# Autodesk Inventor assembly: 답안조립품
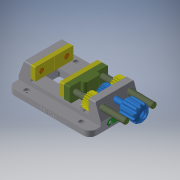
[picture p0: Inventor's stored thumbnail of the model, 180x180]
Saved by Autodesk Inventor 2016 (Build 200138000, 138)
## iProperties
Created: 2021-03
Part Number: 답안조립품
Material: 일반
Document SubType Name: Assembly
Designer: CAD2
Mass: 1539.71 g
Surface Area: 974.157 cm^2
Volume: 352.602 cm^3
Density: 4.3667 g/cm^3
Author: CAD2
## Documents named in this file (10)
- C:\Users\CAD2\Desktop\610306V1014\답안조립품.iam
- C:\Users\CAD2\Desktop\610306V1014\바이스본체 A.ipt
- C:\Users\CAD2\Desktop\610306V1014\고정 플레이트.ipt
- C:\Users\CAD2\Desktop\610306V1014\바이스본체 B.ipt
- C:\Users\CAD2\Desktop\610306V1014\스퍼기어.ipt
- C:\Users\CAD2\Desktop\610306V1014\슬라이딩 부품.ipt
- C:\Users\CAD2\Desktop\610306V1014\십자오목머리나사 M3.ipt
- C:\Users\CAD2\Desktop\610306V1014\십자접시머리나사 M4.ipt
- C:\Users\CAD2\Desktop\610306V1014\지지대.ipt
- C:\Users\CAD2\Desktop\610306V1014\핸들.ipt
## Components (3 placed, 2 different names)
1. 고정 플레이트:1
2. 핸들:1
3. 고정 플레이트:2
